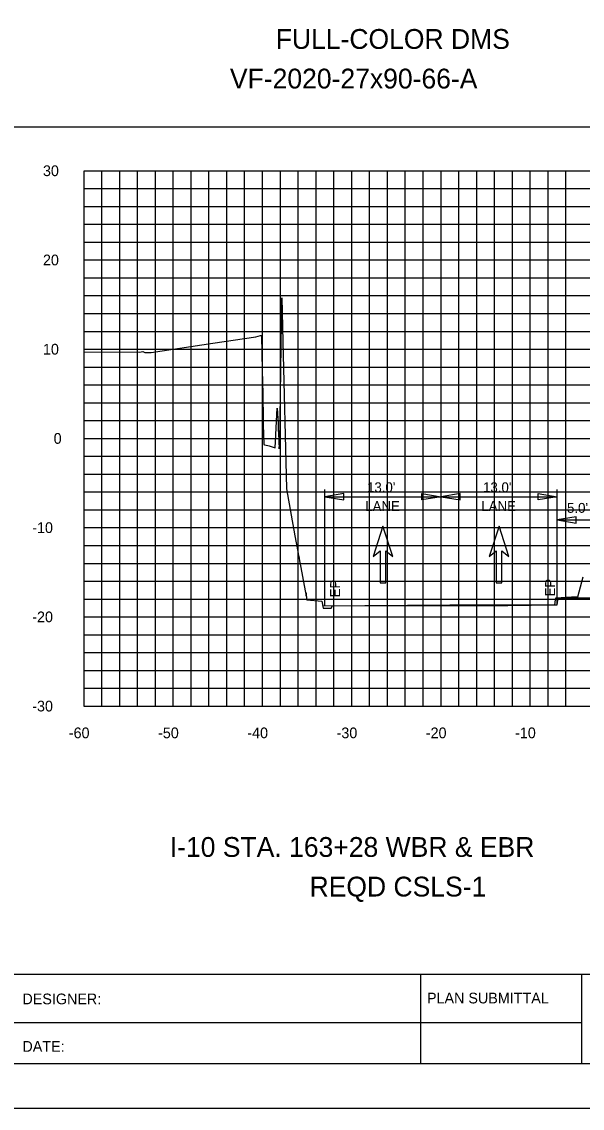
# Model space of a CAD drawing. Extents: x 2193008 to 2198143, y 1236112 to 1237864.
# Drawn here: x 2195321.7 to 2195384.5, y 1237118 to 1237239.8 of the extents above; entities that cross this region are included whole.
import ezdxf

# ---------------------------------------------------------------- set-up
doc = ezdxf.new("R2010")
doc.units = 0
for name, color, linetype in [('10', 7, 'Continuous'), ('3', 7, 'Continuous'), ('31', 7, 'Continuous'), ('60', 7, 'Continuous'), ('ANNO-TXT', 7, 'Continuous'), ('CL-CNST', 7, 'Continuous'), ('GSDIMS', 7, 'Continuous'), ('Level 28', 7, 'Continuous'), ('Level 55', 7, 'Continuous'), ('Level 62', 7, 'Continuous'), ('M-ROADS', 7, 'Continuous'), ('SHT-BDR', 7, 'Continuous'), ('SHT-BNDRY', 7, 'Continuous')]:
    doc.layers.add(name, color=color, linetype=linetype)

msp = doc.modelspace()

# ---------------------------------------------------------------- linework, layer by layer
at = {"layer": '3'}
for p, q in [((2195228.78, 1237228.05), (2195528.78, 1237228.05)), ((2195355.63, 1237174.33), (2195355.63, 1237187.37)), ((2195368.63, 1237174.46), (2195368.63, 1237187.37)), ((2195381.63, 1237174.47), (2195381.63, 1237187.37))]:
    msp.add_line(p, q, dxfattribs=at)
at = {"layer": '60'}
for p, q in [((2195328.63, 1237163.11), (2195328.63, 1237223.11)), ((2195328.63, 1237163.05), (2195328.63, 1237163.11)), ((2195328.63, 1237163.11), (2195448.63, 1237163.11)), ((2195338.63, 1237163.05), (2195338.63, 1237163.11)), ((2195348.63, 1237163.05), (2195348.63, 1237163.11)), ((2195358.63, 1237163.05), (2195358.63, 1237163.11)), ((2195368.63, 1237163.05), (2195368.63, 1237163.11)), ((2195378.63, 1237163.05), (2195378.63, 1237163.11))]:
    msp.add_line(p, q, dxfattribs=at)
at = {"layer": 'CL-CNST'}
msp.add_line((2195381.63, 1237174.47), (2195381.77, 1237175.23), dxfattribs=at)
for points in [[(2195381.77, 1237175.23), (2195391.15, 1237175.23)], [(2195355.37, 1237174.33), (2195369.62, 1237174.47), (2195381.63, 1237174.47)]]:
    msp.add_lwpolyline(points, dxfattribs=at)
at = {"layer": 'GSDIMS'}
for p, q in [((2195355.63, 1237186.58), (2195368.63, 1237186.58)), ((2195368.63, 1237186.58), (2195381.63, 1237186.58)), ((2195381.63, 1237183.98), (2195386.63, 1237183.98))]:
    msp.add_line(p, q, dxfattribs=at)
for points in [[(2195355.63, 1237186.58), (2195357.76, 1237186.23), (2195357.76, 1237186.93)], [(2195368.63, 1237186.58), (2195366.5, 1237186.23), (2195366.5, 1237186.93)], [(2195368.63, 1237186.58), (2195370.76, 1237186.23), (2195370.76, 1237186.93)], [(2195381.63, 1237186.58), (2195379.5, 1237186.23), (2195379.5, 1237186.93)], [(2195381.63, 1237183.98), (2195383.76, 1237183.63), (2195383.76, 1237184.33)]]:
    msp.add_lwpolyline(points, close=True, dxfattribs=at)
at = {"layer": 'Level 28'}
for p, q in [((2195362.13, 1237183.27), (2195361.04, 1237179.87)), ((2195363.22, 1237179.87), (2195362.13, 1237183.27)), ((2195375.13, 1237183.27), (2195374.04, 1237179.87)), ((2195376.22, 1237179.87), (2195375.13, 1237183.27)), ((2195361.04, 1237179.87), (2195361.8, 1237180.51)), ((2195361.8, 1237180.51), (2195361.8, 1237176.94)), ((2195362.46, 1237176.94), (2195362.46, 1237180.51)), ((2195362.46, 1237180.51), (2195363.22, 1237179.87)), ((2195374.04, 1237179.87), (2195374.81, 1237180.51)), ((2195374.81, 1237180.51), (2195374.81, 1237176.94)), ((2195375.46, 1237176.94), (2195375.46, 1237180.51)), ((2195375.46, 1237180.51), (2195376.22, 1237179.87)), ((2195361.8, 1237176.94), (2195362.46, 1237176.94)), ((2195374.81, 1237176.94), (2195375.46, 1237176.94))]:
    msp.add_line(p, q, dxfattribs=at)
at = {"layer": 'Level 62'}
for p, q in [((2195328.63, 1237163.11), (2195328.63, 1237223.11)), ((2195328.63, 1237223.11), (2195448.63, 1237223.11)), ((2195330.63, 1237163.11), (2195330.63, 1237223.11)), ((2195332.63, 1237163.11), (2195332.63, 1237223.11)), ((2195334.63, 1237163.11), (2195334.63, 1237223.11)), ((2195336.63, 1237163.11), (2195336.63, 1237223.11)), ((2195338.63, 1237163.11), (2195338.63, 1237223.11)), ((2195340.63, 1237163.11), (2195340.63, 1237223.11)), ((2195342.63, 1237163.11), (2195342.63, 1237223.11)), ((2195344.63, 1237163.11), (2195344.63, 1237223.11)), ((2195346.63, 1237163.11), (2195346.63, 1237223.11)), ((2195348.63, 1237163.11), (2195348.63, 1237223.11)), ((2195350.63, 1237163.11), (2195350.63, 1237223.11)), ((2195352.63, 1237163.11), (2195352.63, 1237223.11)), ((2195354.63, 1237163.11), (2195354.63, 1237223.11)), ((2195356.63, 1237163.11), (2195356.63, 1237223.11)), ((2195358.63, 1237163.11), (2195358.63, 1237223.11)), ((2195360.63, 1237163.11), (2195360.63, 1237223.11)), ((2195362.63, 1237163.11), (2195362.63, 1237223.11)), ((2195364.63, 1237163.11), (2195364.63, 1237223.11)), ((2195366.63, 1237163.11), (2195366.63, 1237223.11)), ((2195368.63, 1237163.11), (2195368.63, 1237223.11)), ((2195370.63, 1237163.11), (2195370.63, 1237223.11)), ((2195372.63, 1237163.11), (2195372.63, 1237223.11)), ((2195374.63, 1237163.11), (2195374.63, 1237223.11)), ((2195376.63, 1237163.11), (2195376.63, 1237223.11)), ((2195378.63, 1237163.11), (2195378.63, 1237223.11)), ((2195380.63, 1237163.11), (2195380.63, 1237223.11)), ((2195382.63, 1237163.11), (2195382.63, 1237223.11)), ((2195328.63, 1237221.11), (2195448.63, 1237221.11)), ((2195328.63, 1237219.11), (2195448.63, 1237219.11)), ((2195328.63, 1237217.11), (2195448.63, 1237217.11)), ((2195328.63, 1237215.11), (2195448.63, 1237215.11)), ((2195328.63, 1237213.11), (2195448.63, 1237213.11)), ((2195328.63, 1237211.11), (2195448.63, 1237211.11)), ((2195328.63, 1237209.11), (2195448.63, 1237209.11)), ((2195328.63, 1237207.11), (2195448.63, 1237207.11)), ((2195328.63, 1237205.11), (2195448.63, 1237205.11)), ((2195328.63, 1237203.11), (2195448.63, 1237203.11)), ((2195328.63, 1237201.11), (2195448.63, 1237201.11)), ((2195328.63, 1237199.11), (2195448.63, 1237199.11)), ((2195328.63, 1237197.11), (2195448.63, 1237197.11)), ((2195328.63, 1237195.11), (2195448.63, 1237195.11)), ((2195328.63, 1237193.11), (2195448.63, 1237193.11)), ((2195328.63, 1237191.11), (2195448.63, 1237191.11)), ((2195328.63, 1237189.11), (2195448.63, 1237189.11)), ((2195328.63, 1237187.11), (2195448.63, 1237187.11)), ((2195328.63, 1237185.11), (2195448.63, 1237185.11)), ((2195328.63, 1237183.11), (2195448.63, 1237183.11)), ((2195328.63, 1237181.11), (2195448.63, 1237181.11)), ((2195328.63, 1237179.11), (2195448.63, 1237179.11)), ((2195328.63, 1237177.11), (2195448.63, 1237177.11)), ((2195328.63, 1237175.11), (2195448.63, 1237175.11)), ((2195328.63, 1237173.11), (2195448.63, 1237173.11)), ((2195328.63, 1237171.11), (2195448.63, 1237171.11)), ((2195328.63, 1237169.11), (2195448.63, 1237169.11)), ((2195328.63, 1237167.11), (2195448.63, 1237167.11)), ((2195328.63, 1237165.11), (2195448.63, 1237165.11)), ((2195328.63, 1237163.11), (2195448.63, 1237163.11))]:
    msp.add_line(p, q, dxfattribs=at)
msp.add_lwpolyline([(2195203.79, 1237118.04), (2195543.79, 1237118.04), (2195543.79, 1237338.04), (2195203.79, 1237338.04)], close=True, dxfattribs=at)
at = {"layer": 'M-ROADS'}
msp.add_lwpolyline([(2195328.63, 1237202.83), (2195334.85, 1237202.76), (2195335.22, 1237202.85), (2195335.46, 1237202.75), (2195335.61, 1237202.74), (2195335.82, 1237202.74), (2195336.01, 1237202.74), (2195336.17, 1237202.74), (2195343.06, 1237203.79), (2195347.88, 1237204.5), (2195348.42, 1237204.63), (2195348.42, 1237204.63), (2195348.47, 1237204.64), (2195348.48, 1237204.65), (2195348.48, 1237204.65), (2195348.49, 1237204.65), (2195348.49, 1237204.65), (2195348.5, 1237204.65), (2195348.59, 1237200.74), (2195348.65, 1237198.09), (2195348.65, 1237198.06), (2195348.66, 1237197.43), (2195348.7, 1237195.85), (2195348.7, 1237195.5), (2195348.72, 1237194.7), (2195348.72, 1237194.63), (2195348.77, 1237192.44), (2195348.87, 1237192.41), (2195348.87, 1237192.41), (2195348.9, 1237192.4), (2195349.36, 1237192.27), (2195349.38, 1237192.27), (2195350.06, 1237192.07), (2195350.29, 1237196.49), (2195350.37, 1237194.73), (2195350.4, 1237194.04), (2195350.4, 1237193.96), (2195350.41, 1237193.72), (2195350.41, 1237193.69), (2195350.49, 1237191.95), (2195350.5, 1237192.03), (2195350.55, 1237192.39), (2195350.59, 1237192.67), (2195350.79, 1237208.87), (2195350.9, 1237203.98), (2195351.31, 1237187.47), (2195352.27, 1237182.19), (2195352.59, 1237180.44), (2195352.64, 1237180.17), (2195352.73, 1237179.68), (2195352.73, 1237179.67), (2195352.78, 1237179.42), (2195352.78, 1237179.4), (2195352.92, 1237178.65), (2195353.11, 1237177.63), (2195353.51, 1237175.43), (2195353.52, 1237175.81), (2195353.57, 1237175.07), (2195353.59, 1237175.03), (2195353.59, 1237175.02), (2195353.59, 1237175.02), (2195355.28, 1237174.86), (2195355.28, 1237174.86), (2195355.41, 1237174.08), (2195356.32, 1237174.09), (2195356.46, 1237174.34), (2195376.13, 1237174.39), (2195381.39, 1237174.47), (2195381.47, 1237175.01), (2195381.51, 1237175.23), (2195383.27, 1237175.34), (2195383.97, 1237175.37), (2195384.57, 1237177.61)], dxfattribs=at)
at = {"layer": 'SHT-BDR'}
msp.add_lwpolyline([(2195228.78, 1237133.05), (2195528.78, 1237133.05), (2195528.78, 1237323.05), (2195228.78, 1237323.05)], close=True, dxfattribs=at)
at = {"layer": 'SHT-BNDRY'}
for p, q in [((2195366.37, 1237123.04), (2195366.37, 1237133.05)), ((2195384.41, 1237123.04), (2195384.41, 1237133.05)), ((2195228.78, 1237127.65), (2195384.41, 1237127.65))]:
    msp.add_line(p, q, dxfattribs=at)
msp.add_lwpolyline([(2195216.29, 1237123.04), (2195538.79, 1237123.04), (2195538.79, 1237333.04), (2195216.29, 1237333.04)], close=True, dxfattribs=at)

# ---------------------------------------------------------------- texts
at = {"layer": '10'}
for s, p in [('-60', (2195326.93, 1237159.51)), ('-50', (2195336.93, 1237159.51)), ('-40', (2195346.93, 1237159.51)), ('-30', (2195356.93, 1237159.51)), ('-20', (2195366.93, 1237159.51)), ('-10', (2195376.93, 1237159.51))]:
    msp.add_text(s, height=1.2, dxfattribs=at).set_placement(p)
at = {"layer": '31'}
for s, p in [('30', (2195324.03, 1237222.51)), ('20', (2195324.03, 1237212.51)), ('10', (2195324.03, 1237202.51)), ('0', (2195325.23, 1237192.51)), ('-10', (2195322.83, 1237182.51)), ('-20', (2195322.83, 1237172.51)), ('-30', (2195322.83, 1237162.51))]:
    msp.add_text(s, height=1.2, dxfattribs=at).set_placement(p)
at = {"layer": 'ANNO-TXT'}
for s, p in [('DESIGNER:', (2195321.73, 1237129.69)), ('PLAN SUBMITTAL', (2195367.06, 1237129.79)), ('DATE:', (2195321.73, 1237124.37))]:
    msp.add_text(s, height=1.2, rotation=360, dxfattribs=at).set_placement(p)
at = {"layer": 'Level 55'}
for s, height, p in [('FULL-COLOR DMS', 2.2209, (2195350.11, 1237236.77)), ('VF-2020-27x90-66-A', 2.2209, (2195344.98, 1237232.33)), ("13.0'", 1.11, (2195360.34, 1237187.08)), ("13.0'", 1.11, (2195373.34, 1237187.08)), ('LANE', 1.11, (2195360.14, 1237184.97)), ('LANE', 1.11, (2195373.15, 1237184.97)), ("5.0'", 1.11, (2195382.75, 1237184.77)), ('I-10 STA. 163+28 WBR & EBR', 2.2209, (2195338.24, 1237146.21)), ('REQD CSLS-1', 2.2209, (2195353.9, 1237141.77))]:
    msp.add_text(s, height=height, dxfattribs=at).set_placement(p)
for p in [(2195357.32, 1237175.3), (2195381.41, 1237175.4)]:
    msp.add_text('EP', height=1.11, rotation=90, dxfattribs=at).set_placement(p)

doc.saveas('drawing.dxf')
